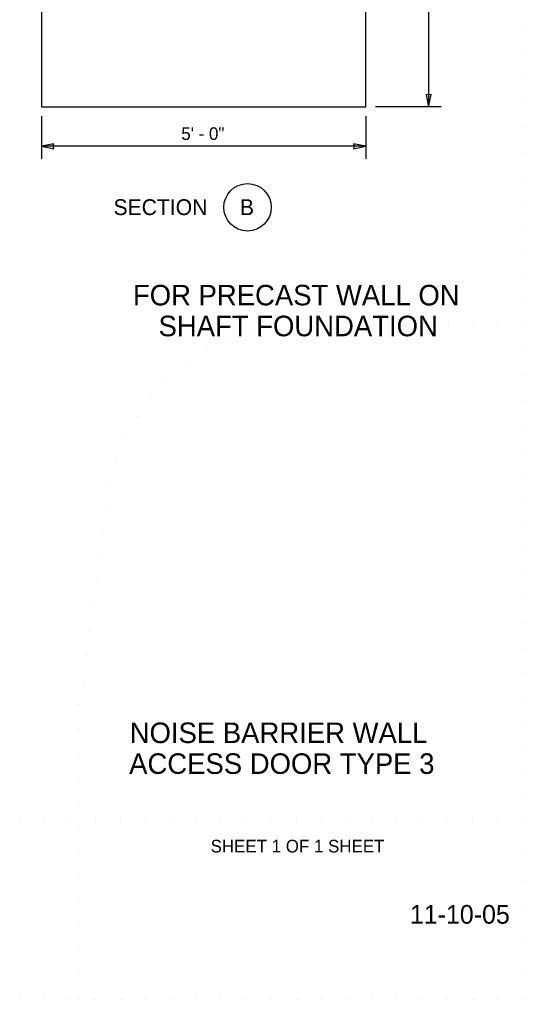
# Model space of a CAD drawing. Extents: x 99862 to 103151, y 100000 to 102076.
# Drawn here: x 102514 to 103150, y 100000 to 101240 of the extents above; entities that cross this region are included whole.
import ezdxf

# ---------------------------------------------------------------- set-up
doc = ezdxf.new("R2010")
doc.units = 0
for name, color, linetype in [('Level 1', 7, 'Continuous'), ('Level 11', 7, 'Continuous'), ('Level 15', 7, 'Continuous'), ('Level 17', 7, 'Continuous'), ('Level 20', 7, 'Continuous'), ('Level 62', 7, 'Continuous'), ('Level 9', 7, 'Continuous')]:
    doc.layers.add(name, color=color, linetype=linetype)

msp = doc.modelspace()

# ---------------------------------------------------------------- linework, layer by layer
at = {"layer": 'Level 1'}
for p, q in [((103150, 101228.4), (103150, 101228.4)), ((103150, 101197), (103150, 101197)), ((103150, 101165.7), (103150, 101165.7)), ((103150, 101134.3), (103150, 101134.3)), ((103150, 101103), (103150, 101103)), ((103150, 101071.6), (103150, 101071.6)), ((103150, 101040.3), (103150, 101040.3)), ((103150, 101008.9), (103150, 101008.9)), ((103150, 100977.5), (103150, 100977.5)), ((103150, 100946.2), (103150, 100946.2)), ((103150, 100914.8), (103150, 100914.8)), ((103150, 100883.5), (103150, 100883.5)), ((102808.5, 100844.4), (102808.5, 100844.4)), ((102839, 100850.2), (102839, 100850.2)), ((102870, 100852.1), (102870, 100852.1)), ((102901.1, 100852.1), (102901.1, 100852.1)), ((102932.3, 100852.1), (102932.3, 100852.1)), ((102963.4, 100852.1), (102963.4, 100852.1)), ((102994.5, 100852.1), (102994.5, 100852.1)), ((103025.6, 100852.1), (103025.6, 100852.1)), ((103056.7, 100852.1), (103056.7, 100852.1)), ((103087.8, 100852.1), (103087.8, 100852.1)), ((103118.9, 100852.1), (103118.9, 100852.1)), ((103150, 100852.1), (103150, 100852.1)), ((103150, 100852.1), (103150, 100852.1)), ((102778.9, 100834.8), (102778.9, 100834.8)), ((102750.8, 100821.5), (102750.8, 100821.5)), ((103150, 100820.8), (103150, 100820.8)), ((102724.6, 100804.8), (102724.6, 100804.8)), ((102700.7, 100784.9), (102700.7, 100784.9)), ((103150, 100789.4), (103150, 100789.4)), ((102679.5, 100762.2), (102679.5, 100762.2)), ((103150, 100758.1), (103150, 100758.1)), ((102661.3, 100737), (102661.3, 100737)), ((103150, 100726.7), (103150, 100726.7)), ((102646.4, 100709.7), (102646.4, 100709.7)), ((103150, 100695.3), (103150, 100695.3)), ((102635.1, 100680.8), (102635.1, 100680.8)), ((103150, 100664), (103150, 100664)), ((102627.6, 100650.6), (102627.6, 100650.6)), ((103150, 100632.6), (103150, 100632.6)), ((102623.1, 100619.8), (102623.1, 100619.8)), ((103150, 100601.3), (103150, 100601.3)), ((102618.9, 100589), (102618.9, 100589)), ((103150, 100569.9), (103150, 100569.9)), ((102614.7, 100558.2), (102614.7, 100558.2)), ((103150, 100538.6), (103150, 100538.6)), ((102610.6, 100527.3), (102610.6, 100527.3)), ((102606.4, 100496.5), (102606.4, 100496.5)), ((103150, 100507.2), (103150, 100507.2)), ((103150, 100475.8), (103150, 100475.8)), ((102602.2, 100465.7), (102602.2, 100465.7)), ((102598, 100434.9), (102598, 100434.9)), ((103150, 100444.5), (103150, 100444.5)), ((103150, 100413.1), (103150, 100413.1)), ((102593.9, 100404), (102593.9, 100404)), ((102589.7, 100373.2), (102589.7, 100373.2)), ((103150, 100381.8), (103150, 100381.8)), ((103150, 100350.4), (103150, 100350.4)), ((102588.7, 100342.2), (102588.7, 100342.2)), ((102588.7, 100311.1), (102588.7, 100311.1)), ((103150, 100319.1), (103150, 100319.1)), ((103150, 100287.7), (103150, 100287.7)), ((102588.7, 100280), (102588.7, 100280)), ((102588.7, 100248.9), (102588.7, 100248.9)), ((103150, 100256.4), (103150, 100256.4)), ((102513.6, 100225), (102513.6, 100225)), ((102545.5, 100225), (102545.5, 100225)), ((102577.3, 100225), (102577.3, 100225)), ((102609.1, 100225), (102609.1, 100225)), ((102640.9, 100225), (102640.9, 100225)), ((102672.7, 100225), (102672.7, 100225)), ((102704.5, 100225), (102704.5, 100225)), ((102736.4, 100225), (102736.4, 100225)), ((102768.2, 100225), (102768.2, 100225)), ((102800, 100225), (102800, 100225)), ((102831.8, 100225), (102831.8, 100225)), ((102863.6, 100225), (102863.6, 100225)), ((102895.5, 100225), (102895.5, 100225)), ((102927.3, 100225), (102927.3, 100225)), ((102959.1, 100225), (102959.1, 100225)), ((102990.9, 100225), (102990.9, 100225)), ((103022.7, 100225), (103022.7, 100225)), ((103054.5, 100225), (103054.5, 100225)), ((103086.4, 100225), (103086.4, 100225)), ((103118.2, 100225), (103118.2, 100225)), ((103150, 100225), (103150, 100225)), ((102588.7, 100217.7), (102588.7, 100217.7)), ((102588.7, 100186.6), (102588.7, 100186.6)), ((103150, 100187.5), (103150, 100187.5)), ((102588.7, 100155.5), (102588.7, 100155.5)), ((103150, 100150), (103150, 100150)), ((102588.7, 100124.4), (102588.7, 100124.4)), ((103150, 100112.5), (103150, 100112.5)), ((102588.7, 100093.3), (102588.7, 100093.3)), ((103150, 100075), (103150, 100075)), ((102588.7, 100062.2), (102588.7, 100062.2)), ((103150, 100037.5), (103150, 100037.5)), ((102588.7, 100031.1), (102588.7, 100031.1)), ((102513.6, 100000), (102513.6, 100000)), ((102545.5, 100000), (102545.5, 100000)), ((102577.3, 100000), (102577.3, 100000)), ((102588.7, 100000), (102588.7, 100000)), ((102609.1, 100000), (102609.1, 100000)), ((102640.9, 100000), (102640.9, 100000)), ((102672.7, 100000), (102672.7, 100000)), ((102704.5, 100000), (102704.5, 100000)), ((102736.4, 100000), (102736.4, 100000)), ((102768.2, 100000), (102768.2, 100000)), ((102800, 100000), (102800, 100000)), ((102831.8, 100000), (102831.8, 100000)), ((102863.6, 100000), (102863.6, 100000)), ((102895.5, 100000), (102895.5, 100000)), ((102927.3, 100000), (102927.3, 100000)), ((102959.1, 100000), (102959.1, 100000)), ((102990.9, 100000), (102990.9, 100000)), ((103022.7, 100000), (103022.7, 100000)), ((103054.5, 100000), (103054.5, 100000)), ((103086.4, 100000), (103086.4, 100000)), ((103118.2, 100000), (103118.2, 100000)), ((103150, 100000), (103150, 100000))]:
    msp.add_line(p, q, dxfattribs=at)
at = {"layer": 'Level 15'}
for p, q in [((103031.3, 101415.2), (103031.3, 101129.3)), ((103047.3, 101129.3), (102963.9, 101129.3)), ((102541.3, 101117.3), (102541.3, 101063.3)), ((102951.9, 101117.3), (102951.9, 101063.3)), ((102951.9, 101079.3), (102541.3, 101079.3))]:
    msp.add_line(p, q, dxfattribs=at)
for points in [[(103031.3, 101129.3), (103034.4, 101145), (103031.3, 101144.3), (103028.2, 101145)], [(102541.3, 101079.3), (102557.1, 101076.2), (102556.3, 101079.3), (102557.1, 101082.4)], [(102951.9, 101079.3), (102936.2, 101082.4), (102936.9, 101079.3), (102936.2, 101076.2)]]:
    msp.add_lwpolyline(points, close=True, dxfattribs=at)
at = {"layer": 'Level 17'}
msp.add_lwpolyline([(102541.3, 101415.2), (102541.3, 101129.3), (102951.9, 101129.3), (102951.9, 101415.2)], dxfattribs=at)
at = {"layer": 'Level 9'}
msp.add_circle((102802.1, 101002.1), 30, dxfattribs=at)

# ---------------------------------------------------------------- texts
at = {"layer": 'Level 11'}
msp.add_text('11-10-05', height=23.62, dxfattribs=at).set_placement((103007.6, 100095.8))
at = {"layer": 'Level 20'}
for s, height, p in [('5\' - 0"', 16, (102718.3, 101087.3)), ('SECTION', 20, (102632.5, 100992.3)), ('B', 20, (102792.5, 100992.3))]:
    msp.add_text(s, height=height, dxfattribs=at).set_placement(p)
at = {"layer": 'Level 62'}
for s, height, p in [('FOR PRECAST WALL ON', 26, (102657.1, 100878)), ('SHAFT FOUNDATION', 26, (102689.5, 100839)), ('NOISE BARRIER WALL', 26, (102653, 100324.3)), ('ACCESS DOOR TYPE 3', 26, (102652.3, 100285.3)), ('SHEET 1 OF 1 SHEET', 16, (102755.4, 100185.9))]:
    msp.add_text(s, height=height, dxfattribs=at).set_placement(p)

doc.saveas('drawing.dxf')
